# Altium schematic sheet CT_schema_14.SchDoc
size 390 x 385 mm
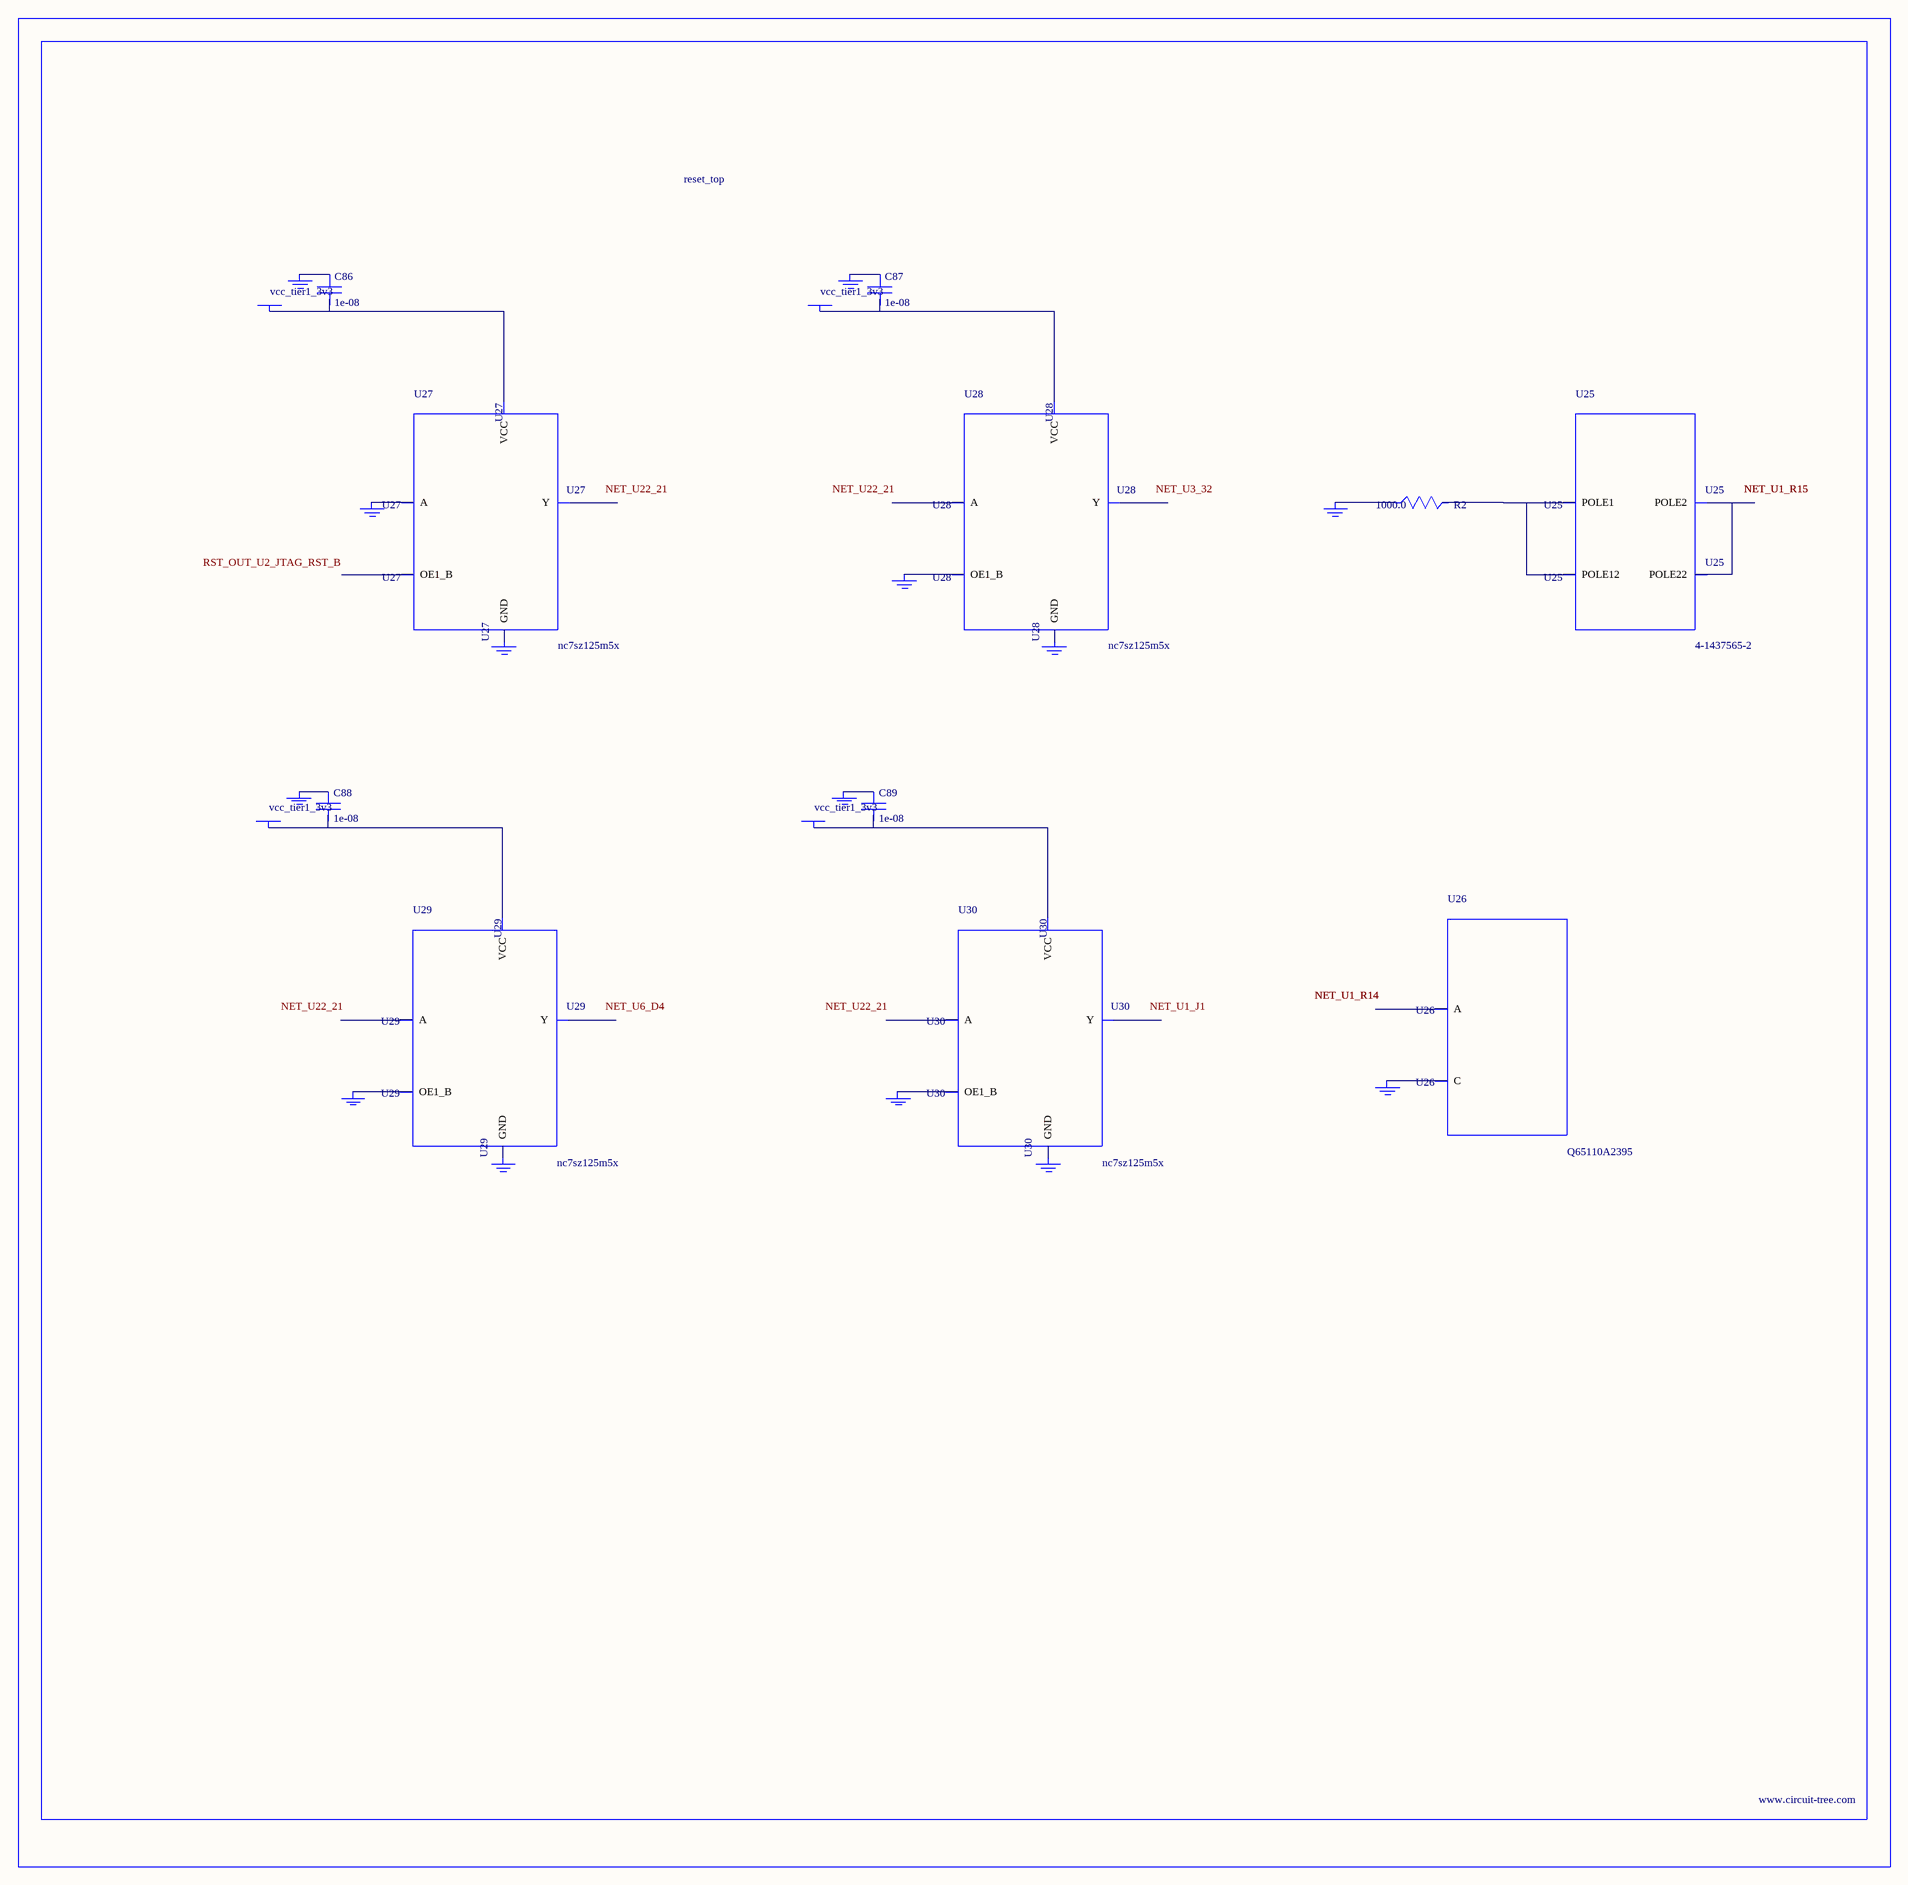
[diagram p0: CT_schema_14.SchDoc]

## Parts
BORDER13  (no value)
C86  1e-08  [C0402]
C87  1e-08  [C0402]
C88  1e-08  [C0402]
C89  1e-08  [C0402]
GND_INSTANCE_13_0  (no value)
GND_INSTANCE_13_1  (no value)
GND_INSTANCE_13_2  (no value)
GND_INSTANCE_13_3  (no value)
GND_INSTANCE_13_4  (no value)
GND_INSTANCE_13_5  (no value)
GND_INSTANCE_13_6  (no value)
GND_INSTANCE_13_7  (no value)
GND_INSTANCE_13_8  (no value)
GND_INSTANCE_13_9  (no value)
GND_INSTANCE_13_10  (no value)
GND_INSTANCE_13_11  (no value)
GND_INSTANCE_13_12  (no value)
GND_INSTANCE_13_13  (no value)
POWER_INSTANCE_13_0  vcc_tier1_3v3
POWER_INSTANCE_13_1  vcc_tier1_3v3
POWER_INSTANCE_13_2  vcc_tier1_3v3
POWER_INSTANCE_13_3  vcc_tier1_3v3
R2  1000.0  [R0603]
U25  4-1437565-2  [SW_4-1437565-2]
U26  Q65110A2395  [LGM67K-G1J2-24-Z]
U27  nc7sz125m5x  [NC7SZ125M5X]
U28  nc7sz125m5x  [NC7SZ125M5X]
U29  nc7sz125m5x  [NC7SZ125M5X]
U30  nc7sz125m5x  [NC7SZ125M5X]

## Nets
NetC86_1: C86.1 GND_INSTANCE_13_2.0(GND)
NetC86_2: C86.2 POWER_INSTANCE_13_0.0(PWR) U27.5(VCC)
NetC87_1: C87.1 GND_INSTANCE_13_5.0(GND)
NetC87_2: C87.2 POWER_INSTANCE_13_1.0(PWR) U28.5(VCC)
NetC88_1: C88.1 GND_INSTANCE_13_8.0(GND)
NetC88_2: C88.2 POWER_INSTANCE_13_2.0(PWR) U29.5(VCC)
NetC89_1: C89.1 GND_INSTANCE_13_11.0(GND)
NetC89_2: C89.2 POWER_INSTANCE_13_3.0(PWR) U30.5(VCC)
NetGND_INSTANCE_13_0_0: GND_INSTANCE_13_0.0(GND) R2.1
NetGND_INSTANCE_13_1_0: GND_INSTANCE_13_1.0(GND) U26.C
NetGND_INSTANCE_13_3_0: GND_INSTANCE_13_3.0(GND) U27.2(A)
NetGND_INSTANCE_13_4_0: GND_INSTANCE_13_4.0(GND) U27.3(GND)
NetGND_INSTANCE_13_6_0: GND_INSTANCE_13_6.0(GND) U28.1(OE1_B)
NetGND_INSTANCE_13_7_0: GND_INSTANCE_13_7.0(GND) U28.3(GND)
NetGND_INSTANCE_13_9_0: GND_INSTANCE_13_9.0(GND) U29.1(OE1_B)
NetGND_INSTANCE_13_10_0: GND_INSTANCE_13_10.0(GND) U29.3(GND)
NetGND_INSTANCE_13_12_0: GND_INSTANCE_13_12.0(GND) U30.1(OE1_B)
NetGND_INSTANCE_13_13_0: GND_INSTANCE_13_13.0(GND) U30.3(GND)
NetR2_2: R2.2 U25.1(POLE1) U25.2(POLE12)
NetU25_3: U25.3(POLE2) U25.4(POLE22)

Not connected (* = marked no-connect by the designer): U26 A; U27 1(OE1_B) 4(Y); U28 2(A) 4(Y); U29 2(A) 4(Y); U30 2(A) 4(Y)

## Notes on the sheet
- Labels drawn without touching a wire or pin: NET_U1_J1, NET_U3_32, NET_U6_D4, NET_U22_21, RST_OUT_U2_JTAG_RST_B

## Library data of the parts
BORDER13 = BORDER_PAGE13
C86-C89 = C0402C103K3RAC
GND_INSTANCE_13_0-GND_INSTANCE_13_13 = GND
POWER_INSTANCE_13_0-POWER_INSTANCE_13_3 = PWR
R2 = RC0603JR-071KL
